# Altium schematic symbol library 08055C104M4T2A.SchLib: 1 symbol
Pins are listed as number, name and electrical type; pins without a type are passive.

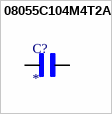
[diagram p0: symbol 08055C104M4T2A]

## 08055C104M4T2A
designator C?
0.1 ÂµF Â±20% 50V Ceramic Capacitor X7R 0805 (2012 Metric); MF: AVX; MP: 08055C104M4T2A
footprint CAPC2012X140N
pins: 1, 2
